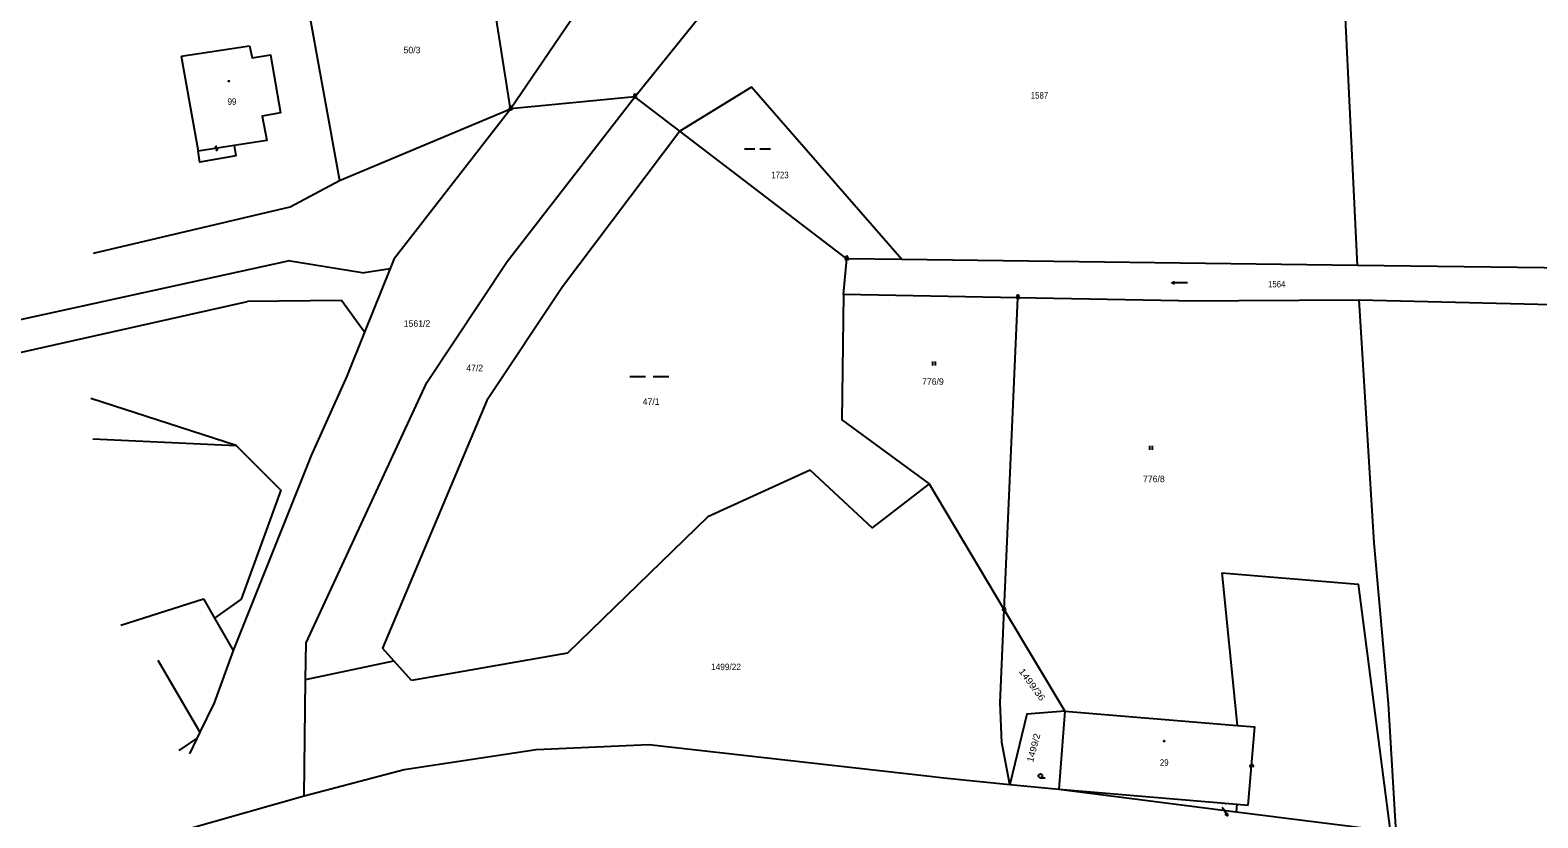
# Model space of a CAD drawing. Extents: x -873052 to -871788, y -1075760 to -1074911.
# Drawn here: x -872962 to -872787.8, y -1075501.4 to -1075410.5 of the extents above; entities that cross this region are included whole.
import ezdxf
from ezdxf.enums import TextEntityAlignment as Align

# ---------------------------------------------------------------- set-up
doc = ezdxf.new("R2010")
doc.units = 0
doc.header["$LTSCALE"] = 0.3
for name, color, linetype, lineweight in [('1', 7, 'Continuous', 25), ('16', 7, 'Continuous', 25), ('24', 7, 'Continuous', 25), ('25', 7, 'Continuous', 25), ('4', 7, 'Continuous', 25)]:
    doc.layers.add(name, color=color, linetype=linetype, lineweight=lineweight)
doc.layers.add('18', color=7, linetype='Continuous')
doc.layers.add('19', color=7, linetype='Continuous')

msp = doc.modelspace()

# ---------------------------------------------------------------- linework, layer by layer
at = {"layer": '1'}
for p, q in [((-872906.47, -1075419.55), (-872895.25, -1075403.04)), ((-872944.52, -1075413.47), (-872936.61, -1075412.26)), ((-872944.52, -1075413.47), (-872942.54, -1075424.44)), ((-872919.91, -1075436.85), (-872906.47, -1075419.55)), ((-872867.64, -1075436.88), (-872886.94, -1075422.12)), ((-873050.08, -1075462.95), (-872932.17, -1075437.09)), ((-872923.61, -1075438.48), (-872932.17, -1075437.09)), ((-872919.91, -1075436.85), (-872920.37, -1075437.98)), ((-872868.01, -1075440.99), (-872867.64, -1075436.88)), ((-872861.28, -1075436.96), (-872867.64, -1075436.88)), ((-872808.66, -1075437.63), (-872861.28, -1075436.96)), ((-873047.36, -1075466.56), (-872936.86, -1075441.8)), ((-872925.99, -1075441.7), (-872936.86, -1075441.8)), ((-872923.35, -1075445.34), (-872925.99, -1075441.7)), ((-872806.74, -1075469.69), (-872808.47, -1075441.61)), ((-872805.05, -1075488.25), (-872806.74, -1075469.69)), ((-872824.32, -1075473.16), (-872822.53, -1075490.76)), ((-872951.51, -1075479.19), (-872941.93, -1075476.16)), ((-872937.58, -1075476.2), (-872940.66, -1075478.37)), ((-872938.51, -1075482.13), (-872940.71, -1075488.17)), ((-872947.2, -1075483.22), (-872942.35, -1075491.56)), ((-872930.15, -1075485.45), (-872919.94, -1075483.3)), ((-872804.17, -1075503.12), (-872805.05, -1075488.25)), ((-872842.46, -1075489.12), (-872843.15, -1075498.14)), ((-872842.46, -1075489.12), (-872822.53, -1075490.76)), ((-872944.74, -1075493.66), (-872942.7, -1075492.29)), ((-872890.51, -1075492.98), (-872858.4, -1075496.58)), ((-872858.4, -1075496.58), (-872856.42, -1075496.82)), ((-872947.53, -1075503.78), (-872930.3, -1075498.9)), ((-872822.59, -1075499.86), (-872822.65, -1075500.74))]:
    msp.add_line(p, q, dxfattribs=at)
for points in [[(-872808.66, -1075437.63), (-872810.64, -1075396.3), (-872771.55, -1075392.17), (-872725.26, -1075387.33), (-872576.3, -1075378.91), (-872564.93, -1075510.69)], [(-872926.22, -1075427.82), (-872906.47, -1075419.55), (-872912.08, -1075384.05)], [(-872892.11, -1075418.17), (-872878.32, -1075401.04), (-872874.29, -1075388.5)], [(-872940.73, -1075404.37), (-872940.07, -1075408.47), (-872930, -1075407.05), (-872926.22, -1075427.82)], [(-872936.61, -1075412.26), (-872936.32, -1075413.66), (-872934.2, -1075413.3), (-872933.05, -1075420.02), (-872935.17, -1075420.38), (-872934.64, -1075423.2), (-872938.39, -1075423.78), (-872938.19, -1075424.97), (-872942.38, -1075425.69), (-872942.54, -1075424.44)], [(-872930.1, -1075481.24), (-872916.14, -1075451.14), (-872906.86, -1075437.18), (-872892.11, -1075418.17)], [(-872886.94, -1075422.12), (-872892.11, -1075418.17), (-872906.47, -1075419.55)], [(-872861.28, -1075436.96), (-872878.63, -1075417.04), (-872886.94, -1075422.12)], [(-872886.94, -1075422.12), (-872900.47, -1075440.09), (-872909.22, -1075453.23), (-872921.26, -1075481.83)], [(-872954.65, -1075436.23), (-872931.95, -1075430.88), (-872926.22, -1075427.82)], [(-872759.52, -1075447.35), (-872759.67, -1075442.71), (-872768.77, -1075442.57), (-872768.62, -1075438.14), (-872808.66, -1075437.63)], [(-872923.61, -1075438.48), (-872920.37, -1075437.98), (-872923.35, -1075445.34), (-872925.4, -1075450.42)], [(-872868.01, -1075440.99), (-872868.22, -1075455.48), (-872858.14, -1075462.85)], [(-872829.27, -1075441.71), (-872847.87, -1075441.36), (-872868.01, -1075440.99)], [(-872848.79, -1075497.58), (-872849.74, -1075492.73), (-872849.93, -1075488.17), (-872849.46, -1075477.4), (-872847.87, -1075441.36)], [(-872829.27, -1075441.71), (-872808.47, -1075441.61), (-872768.77, -1075442.57)], [(-872925.4, -1075450.42), (-872929.49, -1075459.6), (-872938.51, -1075482.13)], [(-872954.73, -1075457.67), (-872938.15, -1075458.45), (-872954.96, -1075453.01)], [(-872938.15, -1075458.45), (-872933, -1075463.59), (-872937.58, -1075476.2)], [(-872858.14, -1075462.85), (-872864.72, -1075467.96), (-872871.86, -1075461.27), (-872883.7, -1075466.67), (-872899.9, -1075482.44), (-872917.92, -1075485.56)], [(-872858.14, -1075462.85), (-872849.46, -1075477.4), (-872842.46, -1075489.12)], [(-872824.32, -1075473.16), (-872808.58, -1075474.44), (-872804.87, -1075502.99), (-872804.17, -1075503.12), (-872769.07, -1075509.49)], [(-872941.93, -1075476.16), (-872940.66, -1075478.37), (-872938.51, -1075482.13)], [(-872930.3, -1075498.9), (-872930.15, -1075485.45), (-872930.1, -1075481.24)], [(-872917.92, -1075485.56), (-872919.94, -1075483.3), (-872921.26, -1075481.83)], [(-872940.71, -1075488.17), (-872942.35, -1075491.56), (-872942.7, -1075492.29), (-872943.55, -1075494.03)], [(-872842.46, -1075489.12), (-872846.83, -1075489.48), (-872848.79, -1075497.58)], [(-872930.3, -1075498.9), (-872918.77, -1075495.86), (-872903.53, -1075493.55), (-872890.51, -1075492.98)], [(-872856.42, -1075496.82), (-872848.79, -1075497.58), (-872843.15, -1075498.14), (-872822.59, -1075499.86)], [(-872843.15, -1075498.14), (-872822.65, -1075500.74), (-872804.87, -1075502.99)]]:
    msp.add_lwpolyline(points, dxfattribs=at)
at = {"layer": '16'}
for p, q in [((-872824.27, -1075500.19), (-872824.13, -1075500.43)), ((-872824.13, -1075500.43), (-872823.671, -1075501.204))]:
    msp.add_line(p, q, dxfattribs=at)
msp.add_lwpolyline([(-872823.695, -1075500.869), (-872823.671, -1075501.204), (-872823.953, -1075501.022)], dxfattribs=at)
at = {"layer": '24'}
for centre, radius in [((-872892.1095, -1075418.1695), 0.1505), ((-872892.1095, -1075418.1695), 0.00652), ((-872906.4695, -1075419.5495), 0.1505), ((-872906.4695, -1075419.5495), 0.00652), ((-872867.6395, -1075436.8795), 0.1505), ((-872867.6395, -1075436.8795), 0.00652), ((-872847.8695, -1075441.3595), 0.1505), ((-872847.8695, -1075441.3595), 0.00652), ((-872849.4595, -1075477.3995), 0.1505), ((-872849.4595, -1075477.3995), 0.00652)]:
    msp.add_circle(centre, radius, dxfattribs=at)
for centre in [(-872892.1096, -1075418.0001), (-872906.4696, -1075419.3801), (-872867.6396, -1075436.7101), (-872847.8696, -1075441.1901), (-872849.4596, -1075477.2301)]:
    msp.add_arc(centre, 0.1311, 328.53402, 210.28963, dxfattribs=at)
at = {"layer": '25'}
for p, q in [((-872879.47, -1075424.15), (-872878.27, -1075424.15)), ((-872877.669, -1075424.15), (-872876.469, -1075424.15)), ((-872828.279, -1075439.64), (-872830.08, -1075439.64)), ((-872857.685, -1075449.199), (-872857.685, -1075448.749)), ((-872857.374, -1075449.199), (-872857.374, -1075448.749)), ((-872892.69, -1075450.47), (-872890.89, -1075450.47)), ((-872889.989, -1075450.47), (-872888.189, -1075450.47)), ((-872832.645, -1075458.919), (-872832.645, -1075458.469)), ((-872832.334, -1075458.919), (-872832.334, -1075458.469)), ((-872845.27, -1075496.82), (-872844.744, -1075496.82))]:
    msp.add_line(p, q, dxfattribs=at)
msp.add_lwpolyline([(-872829.78, -1075439.789), (-872830.08, -1075439.64), (-872829.78, -1075439.489)], dxfattribs=at)
for centre, radius in [((-872938.9995, -1075416.3495), 0.0525), ((-872830.9795, -1075492.5695), 0.0525), ((-872845.2695, -1075496.5945), 0.2255)]:
    msp.add_circle(centre, radius, dxfattribs=at)
for centre, radius, start, end in [((-872940.4753, -1075424.0003), 0.1108, 46.46917, 277.76739), ((-872940.4428, -1075424.2186), 0.11, 225.65498, 98.86541), ((-872820.9898, -1075495.4397), 0.1103, 122.989, 354.80839), ((-872820.7699, -1075495.4601), 0.1105, 302.83095, 175.29353)]:
    msp.add_arc(centre, radius, start, end, dxfattribs=at)
at = {"layer": '4'}
for p, q in [((-872938.39, -1075423.78), (-872942.54, -1075424.44)), ((-872822.53, -1075490.76), (-872820.49, -1075490.93)), ((-872821.26, -1075499.97), (-872820.49, -1075490.93)), ((-872822.59, -1075499.86), (-872821.26, -1075499.97))]:
    msp.add_line(p, q, dxfattribs=at)

# ---------------------------------------------------------------- texts
at = {"layer": '18'}
for s, p in [('50/3', (-872917.8595, -1075413.13)), ('1561/2', (-872917.2795, -1075444.72)), ('47/2', (-872910.6195, -1075449.86)), ('776/9', (-872857.6895, -1075451.42)), ('47/1', (-872890.2395, -1075453.74)), ('776/8', (-872832.1695, -1075462.67))]:
    msp.add_text(s, height=0.75, dxfattribs=at).set_placement(p, align=Align.CENTER)
for s, height, width, p in [('1587', 0.75, 0.9, (-872845.3795, -1075418.365)), ('1723', 0.75, 0.9, (-872875.3595, -1075427.565)), ('1564', 0.75, 0.9, (-872817.9795, -1075440.17)), ('1499/22', 0.75, 0.95, (-872881.5895, -1075484.38)), ('1499/18', 0.1, 0.95, (-872824.07, -1075499.99))]:
    msp.add_text(s, height=height, dxfattribs=dict(at, width=width)).set_placement(p, align=Align.CENTER)
for s, rotation, width, p in [('1499/36', 306.102, 1.2, (-872846.5425, -1075486.2615)), ('1499/2', 75.201, 1.1, (-872845.699, -1075493.4443))]:
    msp.add_text(s, height=0.75, rotation=rotation, dxfattribs=dict(at, width=width)).set_placement(p, align=Align.CENTER)
at = {"layer": '19', "width": 0.9}
for s, p in [('99', (-872938.6495, -1075419.08)), ('29', (-872830.9695, -1075495.43))]:
    msp.add_text(s, height=0.75, dxfattribs=at).set_placement(p, align=Align.CENTER)

doc.saveas('drawing.dxf')
